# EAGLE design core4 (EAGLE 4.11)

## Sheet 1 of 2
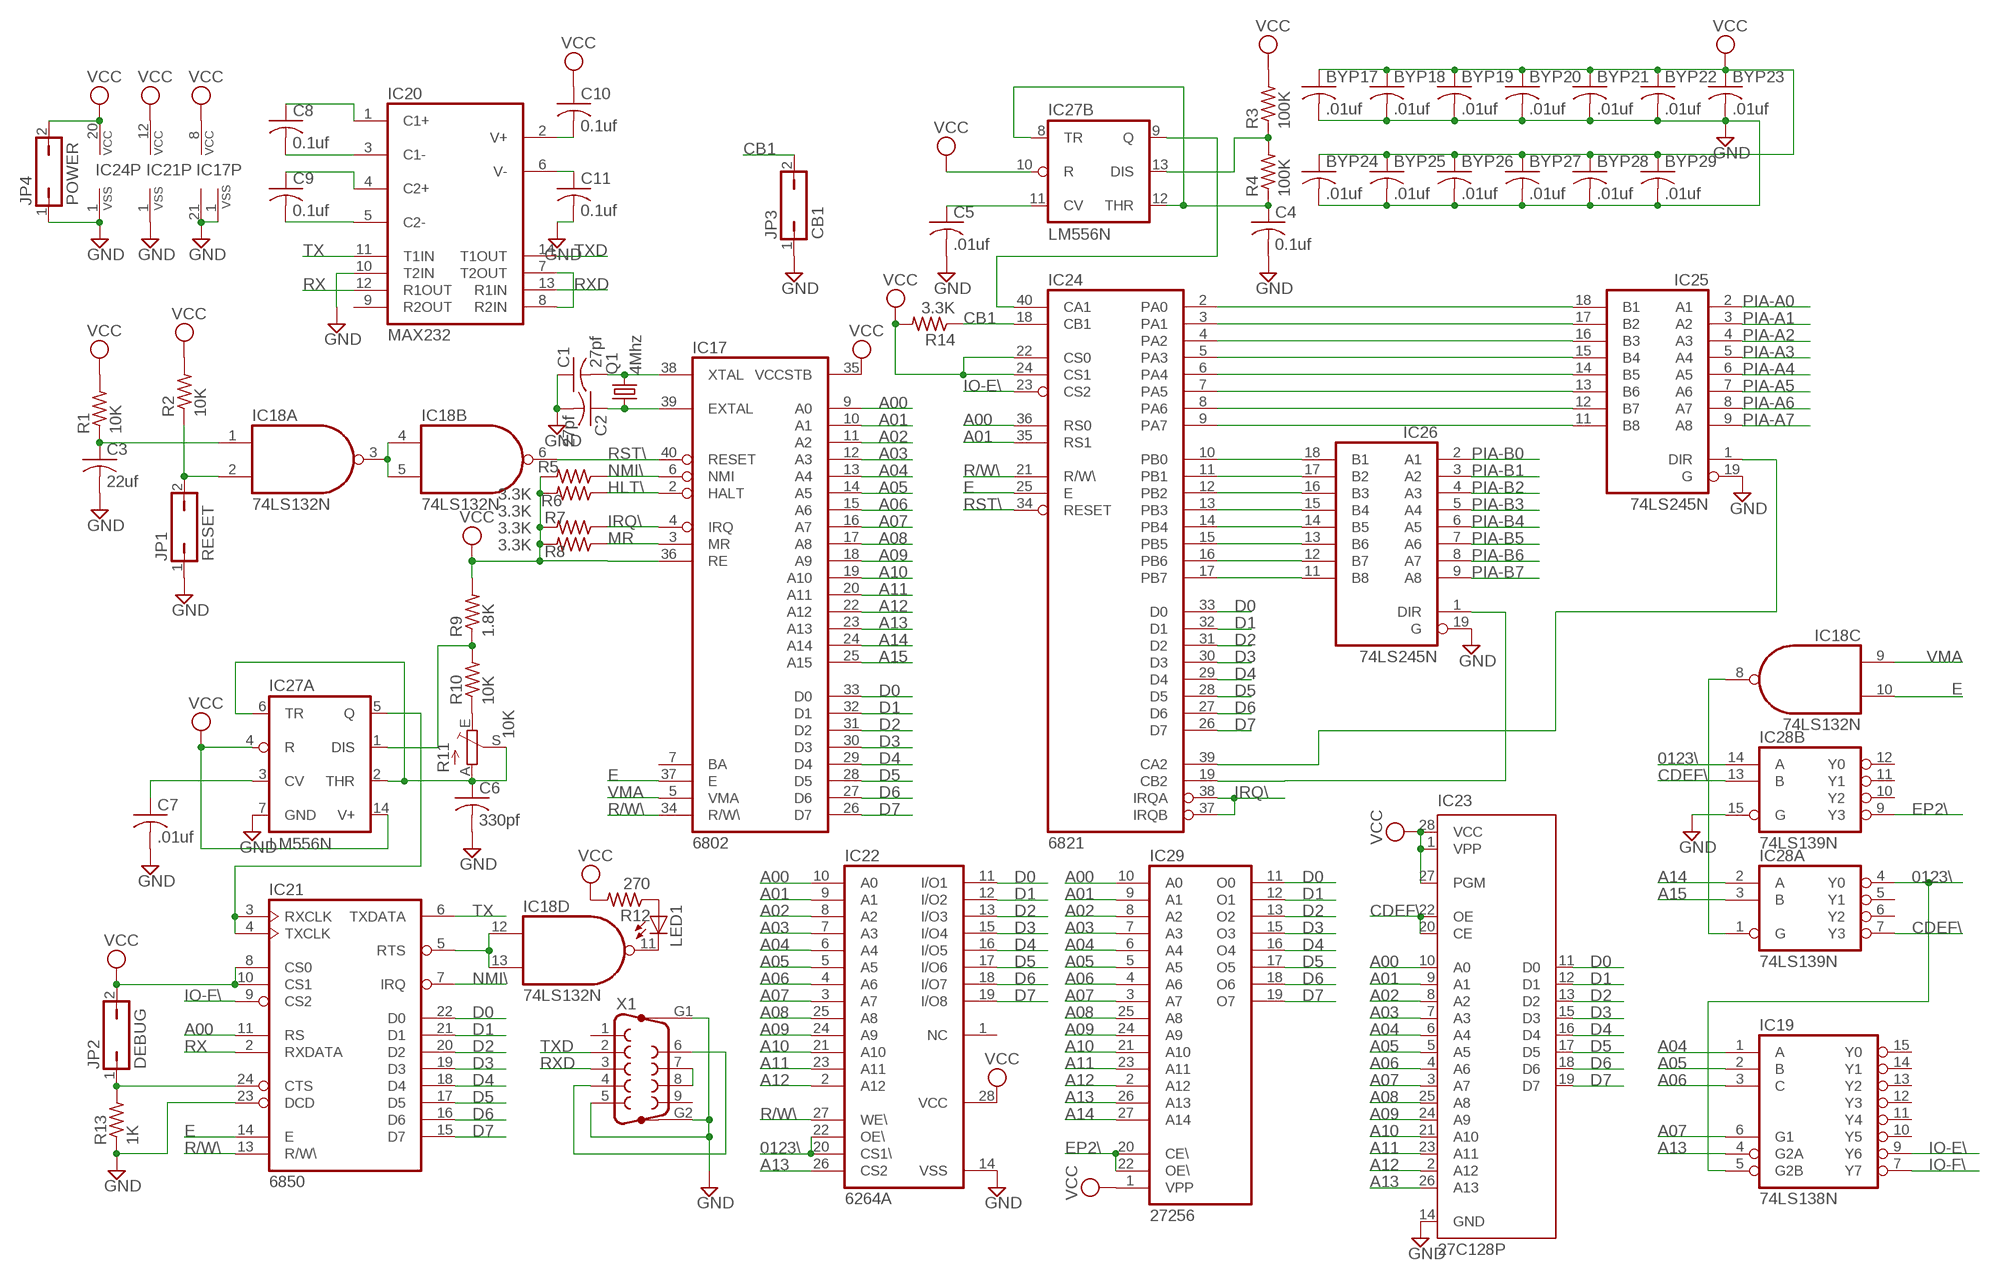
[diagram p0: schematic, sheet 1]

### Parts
BYP17  .01uf  C-US050-025X075  [C050-025X075]
BYP18  .01uf  C-US050-025X075  [C050-025X075]
BYP19  .01uf  C-US050-025X075  [C050-025X075]
BYP20  .01uf  C-US050-025X075  [C050-025X075]
BYP21  .01uf  C-US050-025X075  [C050-025X075]
BYP22  .01uf  C-US050-025X075  [C050-025X075]
BYP23  .01uf  C-US050-025X075  [C050-025X075]
BYP24  .01uf  C-US050-025X075  [C050-025X075]
BYP25  .01uf  C-US050-025X075  [C050-025X075]
BYP26  .01uf  C-US050-025X075  [C050-025X075]
BYP27  .01uf  C-US050-025X075  [C050-025X075]
BYP28  .01uf  C-US050-025X075  [C050-025X075]
BYP29  .01uf  C-US050-025X075  [C050-025X075]
C1  27pf  C-US050-025X075  [C050-025X075]
C2  27pf  C-US050-025X075  [C050-025X075]
C3  22uf  C-US102-043X133  [C102-043X133]
C4  0.1uf  C-US050-025X075  [C050-025X075]
C5  .01uf  C-US050-025X075  [C050-025X075]
C6  330pf  C-US050-025X075  [C050-025X075]
C7  .01uf  C-US050-025X075  [C050-025X075]
C8  0.1uf  C-US050-025X075  [C050-025X075]
C9  0.1uf  C-US050-025X075  [C050-025X075]
C10  0.1uf  C-US050-025X075  [C050-025X075]
C11  0.1uf  C-US050-025X075  [C050-025X075]
IC17  6802  [DIL40]
IC18  74LS132N  74LS00N  [DIL14]
IC19  74LS138N  [DIL16]
IC20  MAX232  [DIL16]
IC21  6850  [DIL24]
IC22  6264A  [DIL28-6]
IC23  27C128P  [DIL28-6]
IC24  6821  [DIL40]
IC25  74LS245N  [DIL20]
IC26  74LS245N  [DIL20]
IC27  LM556N  [DIL14]
IC28  74LS139N  [DIL16]
IC29  27256  [DIL28]
JP1  RESET  JP1Q  [JP1]
JP2  DEBUG  JP1Q  [JP1]
JP3  CB1  JP1Q  [JP1]
JP4  POWER  JP1Q  [JP1]
LED1  LED3MM  [LED3MM]
Q1  4Mhz  CRYTALHC18U-V  [HC18U-V]
R1  10K  R-US_0207/7  [0207/7]
R2  10K  R-US_0207/7  [0207/7]
R3  100K  R-US_0207/7  [0207/7]
R4  100K  R-US_0207/7  [0207/7]
R5  3.3K  R-US_0207/7  [0207/7]
R6  3.3K  R-US_0207/7  [0207/7]
R7  3.3K  R-US_0207/7  [0207/7]
R8  3.3K  R-US_0207/7  [0207/7]
R9  1.8K  R-US_0207/7  [0207/7]
R10  10K  R-US_0207/7  [0207/7]
R11  10K  TRIM_EU-B90P  [SP19L]
R12  270  R-US_0207/7  [0207/7]
R13  1K  R-US_0207/7  [0207/7]
R14  3.3K  R-US_0207/7  [0207/7]
X1  F09HP  [F09HP]

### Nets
0123\: IC19.5(G2B) IC22.20(CS1\) IC22.22(OE\) IC28.4(A:Y0) IC28.14(B:A)
A00: IC17.9(A0) IC21.11(RS) IC22.10(A0) IC23.10(A0) IC24.36(RS0) IC29.10(A0)
A01: IC17.10(A1) IC22.9(A1) IC23.9(A1) IC24.35(RS1) IC29.9(A1)
A02: IC17.11(A2) IC22.8(A2) IC23.8(A2) IC29.8(A2)
A03: IC17.12(A3) IC22.7(A3) IC23.7(A3) IC29.7(A3)
A04: IC17.13(A4) IC19.1(A) IC22.6(A4) IC23.6(A4) IC29.6(A4)
A05: IC17.14(A5) IC19.2(B) IC22.5(A5) IC23.5(A5) IC29.5(A5)
A06: IC17.15(A6) IC19.3(C) IC22.4(A6) IC23.4(A6) IC29.4(A6)
A07: IC17.16(A7) IC19.6(G1) IC22.3(A7) IC23.3(A7) IC29.3(A7)
A08: IC17.17(A8) IC22.25(A8) IC23.25(A8) IC29.25(A8)
A09: IC17.18(A9) IC22.24(A9) IC23.24(A9) IC29.24(A9)
A10: IC17.19(A10) IC22.21(A10) IC23.21(A10) IC29.21(A10)
A11: IC17.20(A11) IC22.23(A11) IC23.23(A11) IC29.23(A11)
A12: IC17.22(A12) IC22.2(A12) IC23.2(A12) IC29.2(A12)
A13: IC17.23(A13) IC19.4(G2A) IC22.26(CS2) IC23.26(A13) IC29.26(A13)
A14: IC17.24(A14) IC28.2(A:A) IC29.27(A14)
A15: IC17.25(A15) IC28.3(A:B)
CB1: IC24.18(CB1) JP3.2 R14.1
CDEF\: IC23.20(CE) IC23.22(OE) IC28.7(A:Y3) IC28.13(B:B)
D0: IC17.33(D0) IC21.22(D0) IC22.11(I/O1) IC23.11(D0) IC24.33(D0) IC29.11(O0)
D1: IC17.32(D1) IC21.21(D1) IC22.12(I/O2) IC23.12(D1) IC24.32(D1) IC29.12(O1)
D2: IC17.31(D2) IC21.20(D2) IC22.13(I/O3) IC23.13(D2) IC24.31(D2) IC29.13(O2)
D3: IC17.30(D3) IC21.19(D3) IC22.15(I/O4) IC23.15(D3) IC24.30(D3) IC29.15(O3)
D4: IC17.29(D4) IC21.18(D4) IC22.16(I/O5) IC23.16(D4) IC24.29(D4) IC29.16(O4)
D5: IC17.28(D5) IC21.17(D5) IC22.17(I/O6) IC23.17(D5) IC24.28(D5) IC29.17(O5)
D6: IC17.27(D6) IC21.16(D6) IC22.18(I/O7) IC23.18(D6) IC24.27(D6) IC29.18(O6)
D7: IC17.26(D7) IC21.15(D7) IC22.19(I/O8) IC23.19(D7) IC24.26(D7) IC29.19(O7)
E: IC17.37(E) IC18.10(C:I1) IC21.14(E) IC24.25(E)
EP2\: IC28.9(B:Y3) IC29.20(CE\) IC29.22(OE\)
GND [Power]: BYP17.2 BYP18.2 BYP19.2 BYP20.2 BYP21.2 BYP22.2 BYP23.2 BYP24.2 BYP25.2 BYP26.2 BYP27.2 BYP28.2 BYP29.2 C1.1 C2.2 C3.2 C4.2 C5.2 C6.2 C7.2 C11.2 IC17.1(VSS) IC17.21(VSS) IC20.10(T2IN) IC21.1(VSS) IC21.23(DCD) IC22.14(VSS) IC23.14(GND) IC24.1(VSS) IC25.19(G) IC26.19(G) IC27.7(A:GND) IC28.15(B:G) JP1.1 JP3.1 JP4.1 R13.1 X1.5 X1.G1 X1.G2 ; also sheet 2
HLT\: IC17.2(HALT) R5.1
IO-E\: IC19.9(Y6) IC24.23(CS2)
IO-F\: IC19.7(Y7) IC21.9(CS2)
IRQ\: IC17.4(IRQ) IC24.37(IRQB) IC24.38(IRQA) R7.1
MR: IC17.3(MR) R8.1
N$3: C2.1 IC17.39(EXTAL) Q1.1
N$4: C1.2 IC17.38(XTAL) Q1.2
N$5: IC24.2(PA0) IC25.18(B1)
N$6: IC18.3(A:O) IC18.4(B:I0) IC18.5(B:I1)
N$21: C3.1 IC18.1(A:I0) R1.1
N$22: IC18.2(A:I1) JP1.2 R2.1
N$23: IC21.3(RXCLK) IC21.4(TXCLK) IC27.5(A:Q)
N$24: IC24.10(PB0) IC26.18(B1)
N$25: IC24.11(PB1) IC26.17(B2)
N$27: C6.1 IC27.2(A:THR) IC27.6(A:TR) R11.A R11.S
N$28: IC27.1(A:DIS) R9.1 R10.2
N$94: IC24.12(PB2) IC26.16(B3)
N$124: IC24.13(PB3) IC26.15(B4)
N$125: IC24.14(PB4) IC26.14(B5)
N$126: IC24.15(PB5) IC26.13(B6)
N$127: IC24.16(PB6) IC26.12(B7)
N$128: IC24.17(PB7) IC26.11(B8)
N$129: IC24.3(PA1) IC25.17(B2)
N$130: IC24.4(PA2) IC25.16(B3)
N$131: IC24.5(PA3) IC25.15(B4)
N$132: IC24.6(PA4) IC25.14(B5)
N$133: IC24.7(PA5) IC25.13(B6)
N$134: IC24.8(PA6) IC25.12(B7)
N$135: IC24.9(PA7) IC25.11(B8)
N$136: IC24.19(CB2) IC26.1(DIR)
N$137: IC24.39(CA2) IC25.1(DIR)
N$138: IC24.40(CA1) IC27.9(B:Q)
N$140: C4.1 IC27.8(B:TR) IC27.12(B:THR) R4.1
N$141: IC27.13(B:DIS) R3.1 R4.2
N$142: C5.1 IC27.11(B:CV)
N$143: R10.1 R11.E
N$144: X1.4 X1.6
N$145: X1.7 X1.8
N$147: IC18.12(D:I0) IC18.13(D:I1) IC21.5(RTS)
N$148: IC18.11(D:O) LED1.K(C)
N$149: LED1.A R12.1
N$150: IC21.24(CTS) JP2.1 R13.2
N$151: IC18.8(C:O) IC28.1(A:G)
N$153: IC20.7(T2OUT) IC20.8(R2IN)
N$154: C7.1 IC27.3(A:CV)
N$155: C9.2 IC20.5(C2-)
N$156: C9.1 IC20.4(C2+)
N$157: C8.2 IC20.3(C1-)
N$158: C8.1 IC20.1(C1+)
N$159: C11.1 IC20.6(V-)
N$160: C10.2 IC20.2(V+)
NMI\: IC17.6(NMI) IC21.7(IRQ) R6.1
PIA-A0: IC25.2(A1) ; also sheet 2
PIA-A1: IC25.3(A2) ; also sheet 2
PIA-A2: IC25.4(A3) ; also sheet 2
PIA-A3: IC25.5(A4) ; also sheet 2
PIA-A4: IC25.6(A5) ; also sheet 2
PIA-A5: IC25.7(A6) ; also sheet 2
PIA-A6: IC25.8(A7) ; also sheet 2
PIA-A7: IC25.9(A8) ; also sheet 2
PIA-B0: IC26.2(A1) ; also sheet 2
PIA-B1: IC26.3(A2) ; also sheet 2
PIA-B2: IC26.4(A3) ; also sheet 2
PIA-B3: IC26.5(A4) ; also sheet 2
PIA-B4: IC26.6(A5) ; also sheet 2
PIA-B5: IC26.7(A6) ; also sheet 2
PIA-B6: IC26.8(A7) ; also sheet 2
PIA-B7: IC26.9(A8) ; also sheet 2
R/W\: IC17.34(R/W\) IC21.13(R/W\) IC22.27(WE\) IC24.21(R/W\)
RST\: IC17.40(RESET) IC18.6(B:O) IC24.34(RESET)
RX: IC20.12(R1OUT) IC21.2(RXDATA)
RXD: IC20.13(R1IN) X1.3
TX: IC20.11(T1IN) IC21.6(TXDATA)
TXD: IC20.14(T1OUT) X1.2
VCC [Power]: BYP17.1 BYP18.1 BYP19.1 BYP20.1 BYP21.1 BYP22.1 BYP23.1 BYP24.1 BYP25.1 BYP26.1 BYP27.1 BYP28.1 BYP29.1 C10.1 IC17.8(VCC) IC17.35(VCCSTB) IC17.36(RE) IC21.8(CS0) IC21.10(CS1) IC21.12(VCC) IC22.28(VCC) IC23.1(VPP) IC23.27(PGM) IC23.28(VCC) IC24.20(VCC) IC24.22(CS0) IC24.24(CS1) IC27.4(A:R) IC27.10(B:R) IC27.14(A:V+) IC29.1(VPP) JP2.2 JP4.2 R1.2 R2.2 R3.2 R5.2 R6.2 R7.2 R8.2 R9.2 R12.2 R14.2 ; also sheet 2
VMA: IC17.5(VMA) IC18.9(C:I0)
Unconnected: IC17.7(BA) IC19.10(Y5) IC19.11(Y4) IC19.12(Y3) IC19.13(Y2) IC19.14(Y1) IC19.15(Y0) IC20.9(R2OUT) IC22.1(NC) IC28.5(A:Y1) IC28.6(A:Y2) IC28.10(B:Y2) IC28.11(B:Y1) IC28.12(B:Y0) X1.1 X1.9

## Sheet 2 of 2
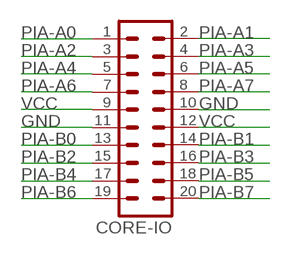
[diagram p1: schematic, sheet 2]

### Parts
CORE-IO  MA10-2  [MA10-2]

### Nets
GND [Power]: CORE-IO.10 CORE-IO.11 ; also sheet 1
PIA-A0: CORE-IO.1 ; also sheet 1
PIA-A1: CORE-IO.2 ; also sheet 1
PIA-A2: CORE-IO.3 ; also sheet 1
PIA-A3: CORE-IO.4 ; also sheet 1
PIA-A4: CORE-IO.5 ; also sheet 1
PIA-A5: CORE-IO.6 ; also sheet 1
PIA-A6: CORE-IO.7 ; also sheet 1
PIA-A7: CORE-IO.8 ; also sheet 1
PIA-B0: CORE-IO.13 ; also sheet 1
PIA-B1: CORE-IO.14 ; also sheet 1
PIA-B2: CORE-IO.15 ; also sheet 1
PIA-B3: CORE-IO.16 ; also sheet 1
PIA-B4: CORE-IO.17 ; also sheet 1
PIA-B5: CORE-IO.18 ; also sheet 1
PIA-B6: CORE-IO.19 ; also sheet 1
PIA-B7: CORE-IO.20 ; also sheet 1
VCC [Power]: CORE-IO.9 CORE-IO.12 ; also sheet 1

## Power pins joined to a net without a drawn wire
GND: IC18.7(P:GND) IC19.8(GND) IC20.15(GND) IC25.10(GND) IC26.10(GND) IC28.8(P:GND) IC29.14(GND)
VCC: IC18.14(P:VCC) IC19.16(VCC) IC20.16(VCC) IC25.20(VCC) IC26.20(VCC) IC28.16(P:VCC) IC29.28(VCC)

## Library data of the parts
BYP17-BYP29 C1-C11 = rcl:C-US: CAPACITOR, American symbol
CORE-IO = con-lstb:MA10-2: PIN HEADER
IC17 = micro-motorola:6802: MICROCONTROLLER/MEMORY DEVICE
IC18 = 74xx-us:74*00: Quad 2-input NAND gate
IC19 = 74xx-us:74*138: 3-line to 8-line DECODER/DEMULTIPLEXER
IC20 = maxim:MAX232: RS232 TRANSEIVER
IC21 = micro-motorola:6850: MICROCONTROLLER/MEMORY DEVICE
IC22 = memory-hitachi:6264A: MEMORY
IC23 = microchip:27*128: CMOS EPROM 128 K (16 K x 8)
IC24 = micro-motorola:6821: MICROCONTROLLER/MEMORY DEVICE
IC25 IC26 = 74xx-us:74*245: Octal BUS TRANSCEIVER, 3-state
IC27 = linear:*556: Dual TIMER
IC28 = 74xx-us:74*139: Dual 2-line to 4-line DECODER/DEMULTIPLEXER
IC29 = memory:27256: MEMORY
JP1-JP4 = jumper:JP1Q: JUMPER
LED1 = led:LED: LED
Q1 = crystal:CRYTAL: CRYSTAL
R1-R10 R12-R14 = rcl:R-US_: RESISTOR, American symbol
R11 = pot:TRIM_EU-: POTENTIOMETER
X1 = con-subd:F09HP: SUB-D

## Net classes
1 Power: width 0.508 mm, drill 0.254 mm, clearance 0.254 mm

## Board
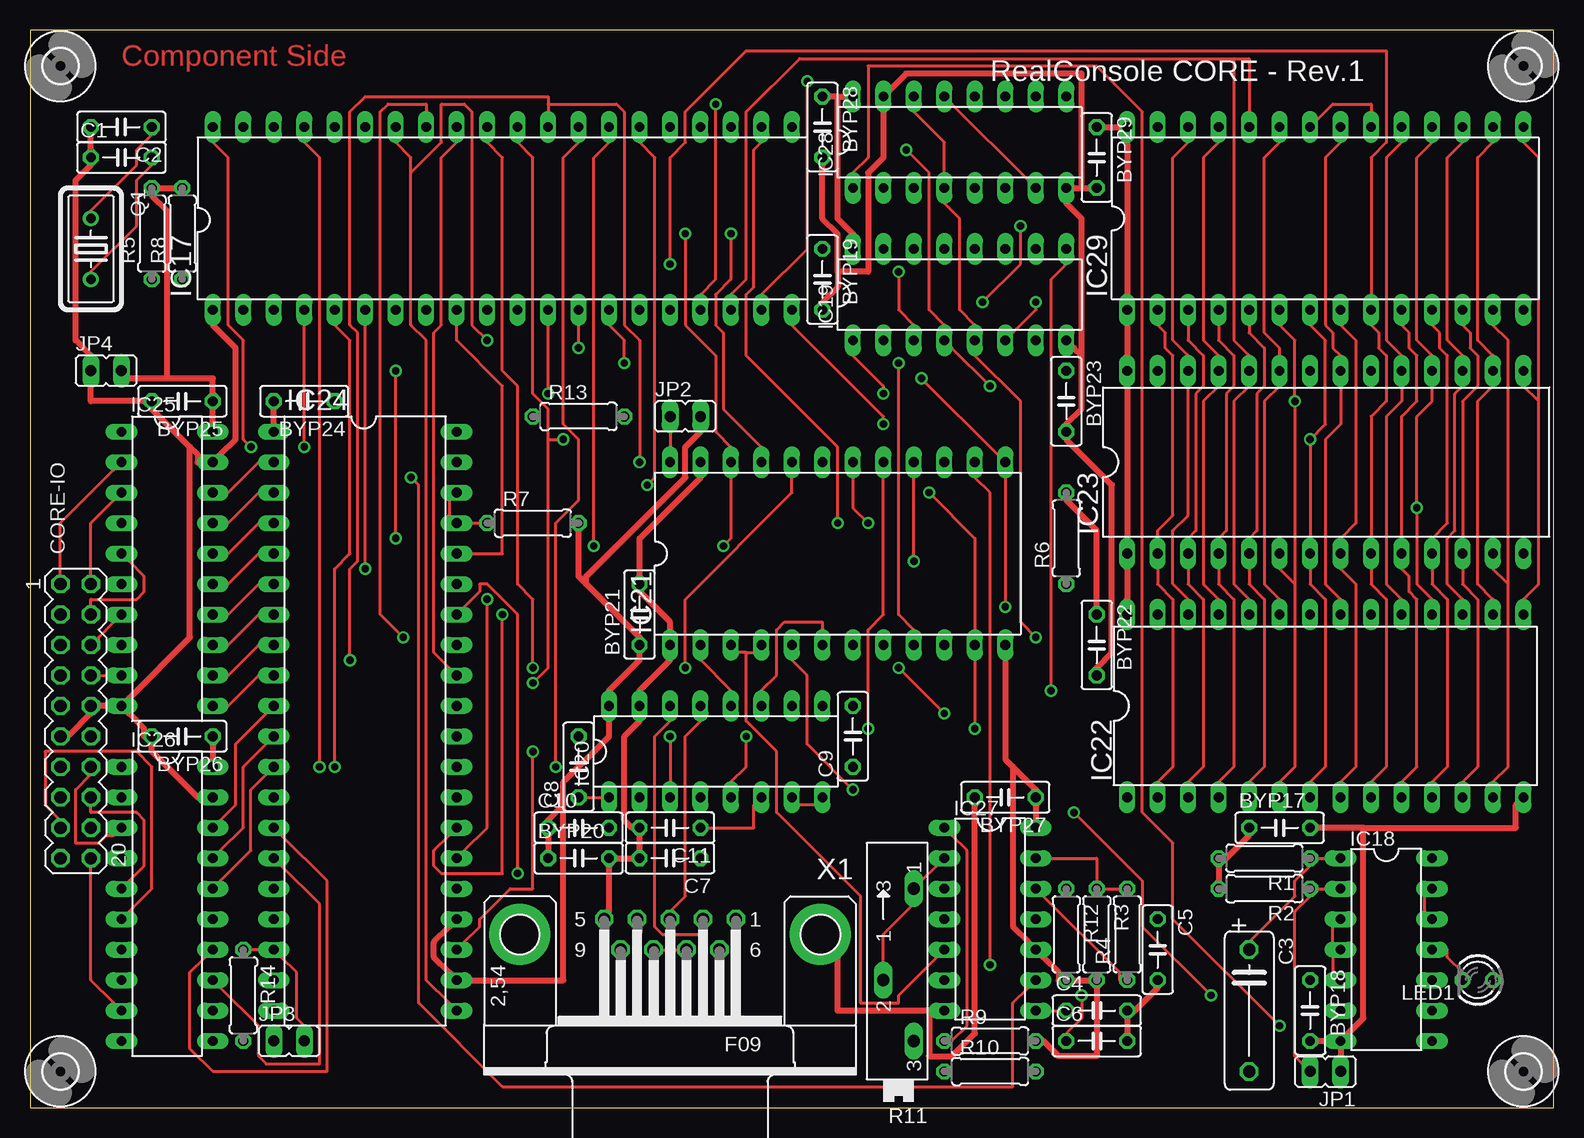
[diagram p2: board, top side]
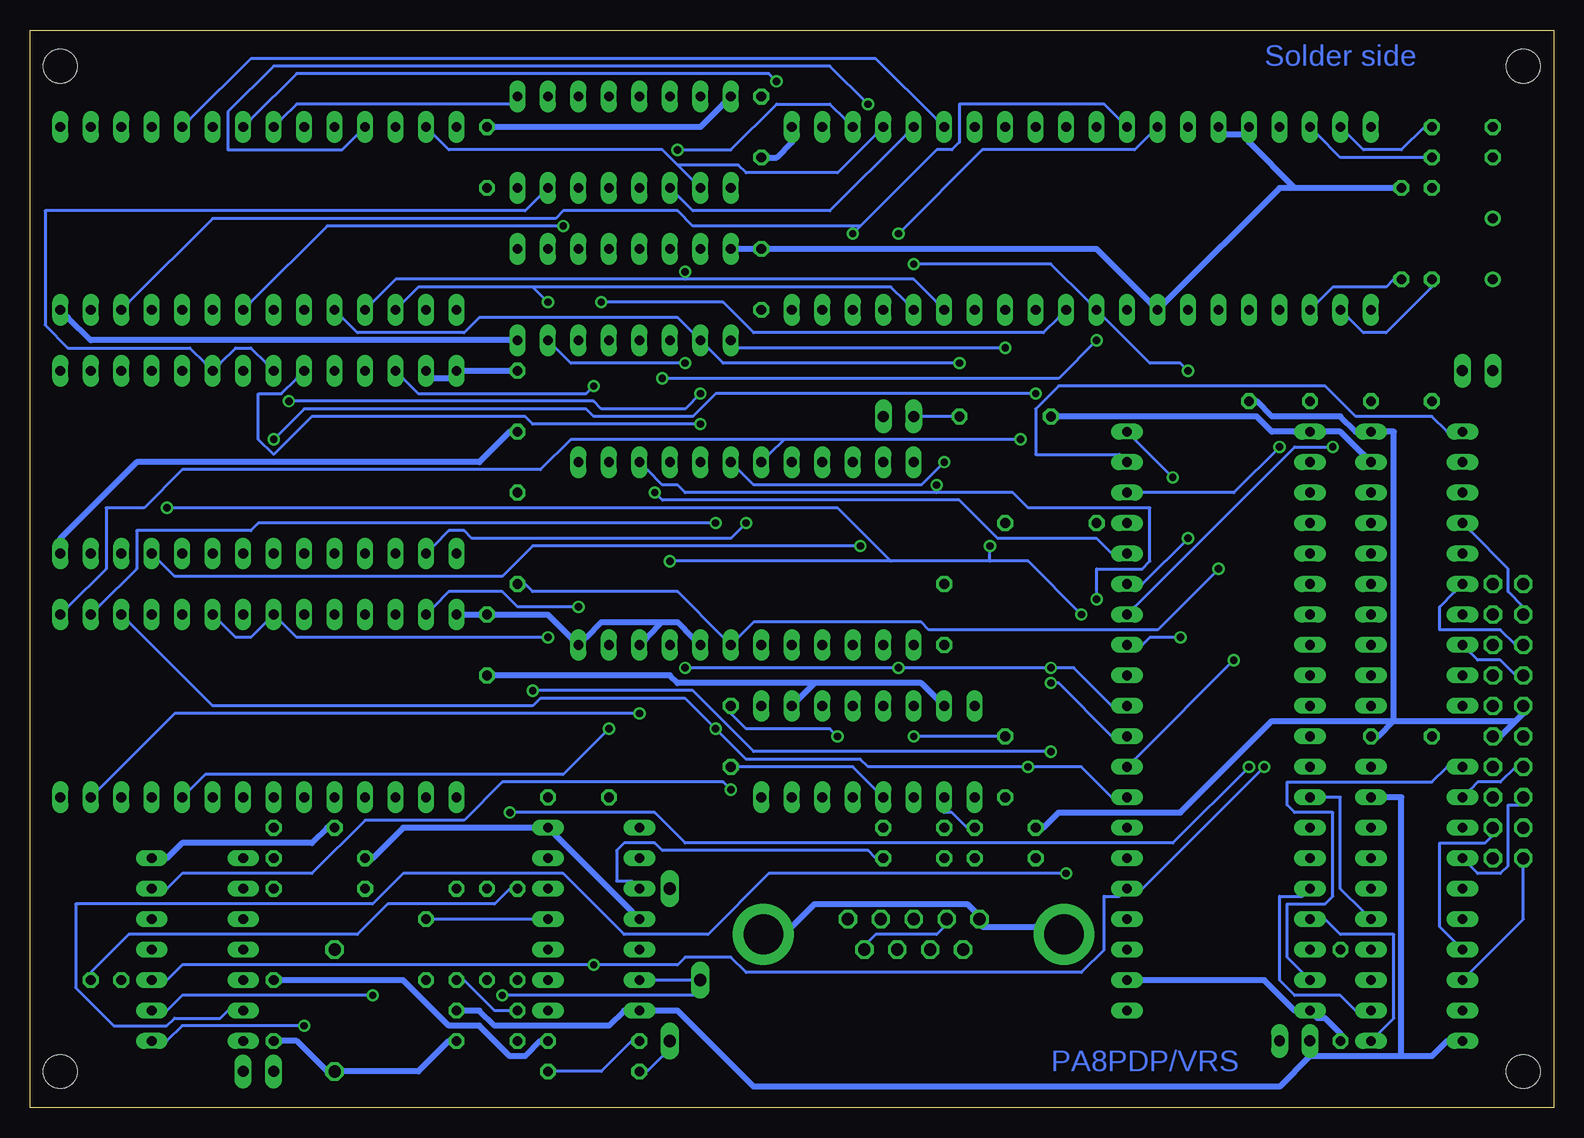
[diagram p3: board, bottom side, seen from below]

Size 126.98 x 89.84 mm. Coordinates in mm from the lower left corner, seen from the top.
Outline: 0,0 126.98,0 126.98,89.84 0,89.84 0,0
Copper layers (1*16): Top 0.035mm / dielectric 1.5mm / Bottom 0.035mm
Design rules "olimex10mil": minimum track width 10mil, minimum drill 24mil, track to track 10mil, track to pad 10mil, pad to pad 10mil, via to via 10mil, smd to smd 10mil, copper to edge 40mil, drill to drill 10mil, minimum pad ring 10mil, minimum via ring 8mil, stop-mask expansion 0mil, vias tented up to drill 0mil, thermal gap 10mil

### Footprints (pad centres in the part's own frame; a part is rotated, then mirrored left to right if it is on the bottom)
C050-025X075 = drill 0.813 octagon: 1 -2.54,0; 2 2.54,0
C102-043X133 = drill 1.016 octagon: 1 -5.08,0; 2 5.08,0
MA10-2 = drill 1.016 octagon: 1 -11.43,-1.27; 2 -11.43,1.27; 3 -8.89,-1.27; 4 -8.89,1.27; 5 -6.35,-1.27; 6 -6.35,1.27; 7 -3.81,-1.27; 8 -3.81,1.27; 9 -1.27,-1.27; 10 -1.27,1.27; 11 1.27,-1.27; 12 1.27,1.27; 13 3.81,-1.27; 14 3.81,1.27; 15 6.35,-1.27; 16 6.35,1.27; 17 8.89,-1.27; 18 8.89,1.27; 19 11.43,-1.27; 20 11.43,1.27
DIL40 = drill 0.813 long: 1 -24.13,-7.62; 2 -21.59,-7.62; 3 -19.05,-7.62; 4 -16.51,-7.62; 5 -13.97,-7.62; 6 -11.43,-7.62; 7 -8.89,-7.62; 8 -6.35,-7.62; 9 -3.81,-7.62; 10 -1.27,-7.62; 11 1.27,-7.62; 12 3.81,-7.62; 13 6.35,-7.62; 14 8.89,-7.62; 15 11.43,-7.62; 16 13.97,-7.62; 17 16.51,-7.62; 18 19.05,-7.62; 19 21.59,-7.62; 20 24.13,-7.62; 21 24.13,7.62; 22 21.59,7.62; 23 19.05,7.62; 24 16.51,7.62; 25 13.97,7.62; 26 11.43,7.62; 27 8.89,7.62; 28 6.35,7.62; 29 3.81,7.62; 30 1.27,7.62; 31 -1.27,7.62; 32 -3.81,7.62; 33 -6.35,7.62; 34 -8.89,7.62; 35 -11.43,7.62; 36 -13.97,7.62; 37 -16.51,7.62; 38 -19.05,7.62; 39 -21.59,7.62; 40 -24.13,7.62
DIL14 = drill 0.813 long: 1 -7.62,-3.81; 2 -5.08,-3.81; 3 -2.54,-3.81; 4 0,-3.81; 5 2.54,-3.81; 6 5.08,-3.81; 7 7.62,-3.81; 8 7.62,3.81; 9 5.08,3.81; 10 2.54,3.81; 11 0,3.81; 12 -2.54,3.81; 13 -5.08,3.81; 14 -7.62,3.81
DIL16 = drill 0.813 long: 1 -8.89,-3.81; 2 -6.35,-3.81; 3 -3.81,-3.81; 4 -1.27,-3.81; 5 1.27,-3.81; 6 3.81,-3.81; 7 6.35,-3.81; 8 8.89,-3.81; 9 8.89,3.81; 10 6.35,3.81; 11 3.81,3.81; 12 1.27,3.81; 13 -1.27,3.81; 14 -3.81,3.81; 15 -6.35,3.81; 16 -8.89,3.81
DIL24 = drill 0.813 long: 1 -13.97,-7.62; 2 -11.43,-7.62; 3 -8.89,-7.62; 4 -6.35,-7.62; 5 -3.81,-7.62; 6 -1.27,-7.62; 7 1.27,-7.62; 8 3.81,-7.62; 9 6.35,-7.62; 10 8.89,-7.62; 11 11.43,-7.62; 12 13.97,-7.62; 13 13.97,7.62; 14 11.43,7.62; 15 8.89,7.62; 16 6.35,7.62; 17 3.81,7.62; 18 1.27,7.62; 19 -1.27,7.62; 20 -3.81,7.62; 21 -6.35,7.62; 22 -8.89,7.62; 23 -11.43,7.62; 24 -13.97,7.62
DIL28-6 = drill 0.813 long: 1 -16.51,-7.62; 2 -13.97,-7.62; 3 -11.43,-7.62; 4 -8.89,-7.62; 5 -6.35,-7.62; 6 -3.81,-7.62; 7 -1.27,-7.62; 8 1.27,-7.62; 9 3.81,-7.62; 10 6.35,-7.62; 11 8.89,-7.62; 12 11.43,-7.62; 13 13.97,-7.62; 14 16.51,-7.62; 15 16.51,7.62; 16 13.97,7.62; 17 11.43,7.62; 18 8.89,7.62; 19 6.35,7.62; 20 3.81,7.62; 21 1.27,7.62; 22 -1.27,7.62; 23 -3.81,7.62; 24 -6.35,7.62; 25 -8.89,7.62; 26 -11.43,7.62; 27 -13.97,7.62; 28 -16.51,7.62
DIL20 = drill 0.813 long: 1 -11.43,-3.81; 2 -8.89,-3.81; 3 -6.35,-3.81; 4 -3.81,-3.81; 5 -1.27,-3.81; 6 1.27,-3.81; 7 3.81,-3.81; 8 6.35,-3.81; 9 8.89,-3.81; 10 11.43,-3.81; 11 11.43,3.81; 12 8.89,3.81; 13 6.35,3.81; 14 3.81,3.81; 15 1.27,3.81; 16 -1.27,3.81; 17 -3.81,3.81; 18 -6.35,3.81; 19 -8.89,3.81; 20 -11.43,3.81
DIL28 = drill 0.813 long: 1 -16.51,-7.62; 2 -13.97,-7.62; 3 -11.43,-7.62; 4 -8.89,-7.62; 5 -6.35,-7.62; 6 -3.81,-7.62; 7 -1.27,-7.62; 8 1.27,-7.62; 9 3.81,-7.62; 10 6.35,-7.62; 11 8.89,-7.62; 12 11.43,-7.62; 13 13.97,-7.62; 14 16.51,-7.62; 15 16.51,7.62; 16 13.97,7.62; 17 11.43,7.62; 18 8.89,7.62; 19 6.35,7.62; 20 3.81,7.62; 21 1.27,7.62; 22 -1.27,7.62; 23 -3.81,7.62; 24 -6.35,7.62; 25 -8.89,7.62; 26 -11.43,7.62; 27 -13.97,7.62; 28 -16.51,7.62
JP1 = drill 0.914 long: 1 0,-1.27; 2 0,1.27
LED3MM = drill 0.813 octagon: A -1.27,0; K 1.27,0
HC18U-V = drill 0.813 round: 1 -2.54,0; 2 2.54,0
0207/7 = drill 0.813 octagon: 1 -3.81,0; 2 3.81,0
SP19L = drill 1.016 long: A 5.715,-1.27; E -6.985,-1.27; S -1.905,1.27
2,8 = hole 2.8: 0,0
F09HP = drill 1.016 octagon: 1 -5.486,-1.27; 2 -2.743,-1.27; 3 0,-1.27; 4 2.743,-1.27; 5 5.486,-1.27; 6 -4.115,1.27; 7 -1.372,1.27; 8 1.372,1.27; 9 4.115,1.27 | drill 3.302 pad 5.08 round: G1 -12.522,0; G2 12.522,0

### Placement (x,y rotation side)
BYP17  104.14,23.33 0 top
BYP18  106.68,8.09 270 top
BYP19  66.04,69.05 270 top
BYP20  45.71,20.79 0 top
BYP21  50.79,41.11 90 top
BYP22  88.9,38.57 270 top
BYP23  86.36,58.89 270 top
BYP24  22.86,58.89 180 top
BYP25  12.69,58.89 180 top
BYP26  12.69,30.95 180 top
BYP27  81.28,25.87 180 top
BYP28  66.04,81.75 270 top
BYP29  88.9,79.21 270 top
C1  7.62,79.21 0 top
C2  7.62,81.75 180 top
C3  101.59,8.09 270 top
C4  88.9,8.09 0 top
C5  93.98,13.17 270 top
C6  88.9,5.55 0 top
C7  53.34,20.79 180 top
C8  45.71,28.41 90 top
C9  68.58,30.95 90 top
C10  45.71,23.33 0 top
C11  53.34,23.33 180 top
CORE-IO  3.81,32.22 270 top
IC17  39.36,74.13 0 top
IC18  113.03,13.17 270 top
IC19  77.47,67.78 0 top
IC20  57.14,29.68 0 top
IC21  67.31,46.19 0 top
IC22  107.95,33.49 0 top
IC23  107.95,53.81 0 top
IC24  27.94,32.22 270 top
IC25  11.42,44.92 270 top
IC26  11.42,16.98 270 top
IC27  80.01,15.71 270 top
IC28  77.47,80.48 0 top
IC29  107.95,74.13 0 top
JP1  107.95,3.01 90 top
JP2  54.6,57.62 270 top
JP3  21.59,5.55 270 top
JP4  6.34,61.43 270 top
LED1  120.65,10.63 180 top
Q1  5.08,71.59 270 top
R1  102.87,20.79 180 top
R2  102.87,18.25 180 top
R3  88.9,14.44 270 top
R4  91.44,14.44 90 top
R5  10.15,72.86 90 top
R6  86.36,47.46 90 top
R7  41.9,48.73 0 top
R8  12.69,72.86 90 top
R9  80.01,5.55 0 top
R10  80.01,3.01 0 top
R11  72.39,12.54 90 top
R12  86.36,14.44 270 top
R13  45.71,57.62 0 top
R14  17.78,9.36 270 top
U$3  [2,8]  2.54,86.83 0 top
U$4  [2,8]  2.54,3.01 0 top
U$5  [2,8]  124.45,86.83 0 top
U$6  [2,8]  124.45,3.01 0 top
X1  53.34,14.44 180 top

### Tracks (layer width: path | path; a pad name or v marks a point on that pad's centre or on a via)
0123\  (via drill 0.61)
  Top 0.254: IC28.14 73.66,83.02 76.2,80.48 76.2,77.94 IC28.4 76.2,75.4 77.47,74.13 77.47,66.51 78.73,65.24 IC19.5 78.73,62.7 82.55,58.89 82.55,40.48 v83.81,39.2
  Bottom 0.254: IC22.20 111.12,40.48 109.85,39.2 108.58,39.2 107.31,40.48 IC22.22 106.04,40.48 104.77,39.2 v83.81,39.2
A00  (via drill 0.61)
  Top 0.254: IC24.36 36.82,46.19 39.36,46.19 39.36,60.16 35.55,63.97 35.55,65.24 IC17.9 | v78.73,31.58 78.73,37.3 IC21.11 78.73,39.84 78.73,47.46 v74.93,51.27 | IC22.10 114.3,27.14 115.56,28.41 115.56,42.38 114.93,43.02 114.93,44.28 114.3,44.92 IC23.10 114.3,47.46 114.3,57.62 115.56,58.89 115.56,62.7 114.93,63.34 114.93,64.61 114.3,65.24 IC29.10
  Bottom 0.254: v78.73,31.58 82.55,27.77 112.39,27.77 113.66,26.5 IC22.10 | v74.93,51.27 74.29,50.63 49.52,50.63 46.35,47.46 38.09,47.46 36.82,46.19 IC24.36
A01  (via drill 0.61)
  Top 0.254: v30.48,47.46 v30.48,61.43 | IC22.9 111.76,27.14 113.03,28.41 113.03,42.38 111.76,43.65 111.76,44.92 IC23.9 111.76,47.46 111.76,57.62 113.03,58.89 113.03,62.7 112.39,63.34 112.39,64.61 111.76,65.24 IC29.9 111.76,67.78 111.76,79.21 113.03,80.48 113.03,88.1 59.68,88.1 54.6,83.02 54.6,80.48 53.34,79.21 v53.34,70.32
  Bottom 0.254: v30.48,47.46 34.28,43.65 IC24.35 | v30.48,61.43 31.11,62.06 33.65,62.06 37.46,65.88 IC17.10 38.73,67.14 41.9,70.32 v53.34,70.32
A02  (via drill 0.61)
  Top 0.254: IC22.8 109.22,27.14 110.48,28.41 110.48,43.65 109.22,44.92 IC23.8 109.22,47.46 110.48,48.73 110.48,63.97 109.22,65.24 IC29.8 | v79.37,67.14 82.55,70.32 v82.55,73.5
  Bottom 0.254: v79.37,67.14 69.21,67.14 66.67,64.61 42.54,64.61 41.27,65.88 IC17.11 | v82.55,73.5 102.23,73.5 108.58,67.14 IC29.8
A03  (via drill 0.61)
  Top 0.254: IC22.7 106.68,27.14 107.95,28.41 107.95,42.38 106.68,43.65 106.68,44.92 IC23.7 106.68,47.46 v106.68,55.71 107.95,56.98 107.95,63.97 106.68,65.24 IC29.7 | v43.17,59.52 43.17,65.24 IC17.12
  Bottom 0.254: v43.17,59.52 69.84,59.52 71.75,57.62 80.01,57.62 80.64,58.25 104.14,58.25 v106.68,55.71
A04  (via drill 0.61)
  Top 0.254: v45.71,63.34 45.71,65.24 IC17.13 | 105.41,43.65 105.41,28.41 104.14,27.14 IC22.6 | 105.41,43.65 104.14,44.92 IC23.6 | 105.41,43.65 v105.41,58.89 105.41,63.97 104.14,65.24 IC29.6 | v71.12,59.52 71.12,60.16 68.58,62.7 IC19.1
  Bottom 0.254: v45.71,63.34 67.94,63.34 IC19.1 | v71.12,59.52 72.39,58.25 79.37,58.25 80.01,58.89 v105.41,58.89
A05  (via drill 0.61)
  Top 0.254: IC22.5 101.59,27.14 102.87,28.41 102.87,42.38 101.59,43.65 101.59,44.92 IC23.5 101.59,47.46 102.23,48.09 102.23,59.52 102.87,60.16 102.87,63.34 101.59,64.61 101.59,65.24 IC29.5 | v49.52,62.06 49.52,63.97 48.25,65.24 IC17.14
  Bottom 0.254: IC29.5 100.96,65.88 99.69,64.61 90.8,64.61 89.53,65.88 73.02,65.88 71.75,64.61 IC19.2 70.48,63.34 69.21,62.06 v49.52,62.06
A06  (via drill 0.61)
  Top 0.254: IC22.4 99.06,27.14 100.33,28.41 100.33,42.38 99.06,43.65 99.06,44.92 IC23.4 99.06,47.46 99.69,48.09 99.69,59.52 100.33,60.16 100.33,62.7 99.06,63.97 99.06,65.24 IC29.4 | v72.39,69.69 72.39,66.51 73.66,65.24 IC19.3
  Bottom 0.254: 72.39,69.05 96.52,69.05 98.42,67.14 IC29.4 | 72.39,69.05 53.34,69.05 51.43,67.14 IC17.15 | 72.39,69.05 v72.39,69.69
A07  (via drill 0.61)
  Top 0.254: IC22.3 96.52,27.14 97.79,28.41 97.79,42.38 96.52,43.65 96.52,44.92 IC23.3 96.52,47.46 97.15,48.09 97.15,59.52 97.79,60.16 97.79,62.7 96.52,63.97 96.52,65.24 IC29.3 | v83.81,67.14 83.81,66.51 81.91,64.61 IC19.6
  Bottom 0.254: 85.09,68.41 v83.81,67.14 | 85.09,68.41 94.61,68.41 95.88,67.14 IC29.3 | 85.09,68.41 55.24,68.41 53.97,67.14 IC17.16
A08  (via drill 0.61)
  Top 0.254: IC22.25 99.06,42.38 97.79,43.65 97.79,58.89 99.06,60.16 IC23.25 99.06,62.7 97.79,63.97 97.79,79.21 99.06,80.48 IC29.25 | v57.14,83.66 57.14,69.05 55.88,67.78 IC17.17
  Bottom 0.254: v57.14,83.66 60.32,86.83 106.68,86.83 110.48,83.02 110.48,79.84 100.96,79.84 99.69,81.11 IC29.25
A09
  Top 0.254: IC22.24 101.59,42.38 100.33,43.65 100.33,58.89 101.59,60.16 IC23.24 101.59,62.7 100.33,63.97 100.33,87.47 | 100.33,87.47 101.59,87.47 101.59,83.02 IC29.24 | 100.33,87.47 64.13,87.47 59.68,83.02 59.68,69.05 58.41,67.78 IC17.18
A10  (via drill 0.61)
  Top 0.254: IC22.21 109.22,42.38 107.95,43.65 107.95,55.71 109.22,56.98 109.22,60.16 IC23.21 109.22,62.7 108.58,63.34 108.58,64.61 107.95,65.24 107.95,79.21 109.22,80.48 IC29.21 | v64.77,85.56 64.77,71.59 60.95,67.78 IC17.19
  Bottom 0.254: v64.77,85.56 65.4,86.19 104.77,86.19 108.58,82.39 IC29.21
A11  (via drill 0.61)
  Top 0.254: IC22.23 104.14,42.38 102.87,43.65 102.87,58.89 104.14,60.16 IC23.23 104.14,62.7 104.14,63.34 102.87,64.61 102.87,79.21 104.14,80.48 IC29.23 | v71.12,56.98 71.12,57.62 63.49,65.24 IC17.20
  Bottom 0.254: v71.12,56.98 85.09,56.98 85.72,57.62 103.5,57.62 106.68,54.45 107.95,55.71 107.95,59.52 106.04,59.52 104.77,60.8 IC23.23
A12  (via drill 0.61)
  Top 0.254: IC22.2 93.98,27.14 95.25,28.41 95.25,42.38 93.98,43.65 93.98,44.92 IC23.2 93.98,47.46 93.98,48.09 95.25,49.37 95.25,62.7 94.61,63.34 94.61,64.61 93.98,65.24 IC29.2 | v67.31,48.73 67.31,55.08 59.68,62.7 59.68,67.78 60.32,68.41 60.32,79.84 60.95,80.48 IC17.22
  Bottom 0.254: v67.31,48.73 68.58,47.46 90.17,47.46 90.8,48.09 92.07,48.09 93.34,46.82 IC23.2
A13  (via drill 0.61)
  Top 0.254: v73.02,79.84 74.93,77.94 74.93,66.51 76.2,65.24 IC19.4 76.83,63.34 v80.01,60.16 | IC22.26 96.52,42.38 95.25,43.65 95.25,48.09 96.52,49.37 96.52,60.16 IC23.26 96.52,62.7 95.25,63.97 95.25,79.21 96.52,80.48 IC29.26
  Bottom 0.254: v73.02,79.84 68.58,79.84 64.77,83.66 60.32,83.66 59.05,82.39 IC17.23 | v80.01,60.16 80.64,59.52 94.61,59.52 95.88,60.8 IC23.26
A14
  Bottom 0.254: 73.02,78.58 74.29,79.84 92.07,79.84 93.34,81.11 IC29.27 | 73.02,78.58 71.75,77.3 IC28.2 | 73.02,78.58 67.94,78.58 67.31,77.94 59.68,77.94 56.51,81.11 IC17.24
A15
  Bottom 0.254: IC17.25 53.97,81.11 60.32,74.77 71.75,74.77 73.02,76.03 IC28.3
CB1
  Top 0.254: R14.1 18.41,13.17 19.05,13.17 IC24.18 20.95,12.54 22.22,11.27 22.22,7.46 22.86,6.82 JP3.2
CDEF\
  Top 0.254: IC28.13 76.83,83.66 83.18,77.3 IC28.7
  Bottom 0.254: IC23.22 107.31,62.06 108.58,63.34 109.85,63.34 111.12,62.06 IC23.20 112.39,62.06 113.66,63.34 123.82,63.34 125.73,65.24 125.73,74.77 85.72,74.77 84.45,76.03 IC28.7
D0  (via drill 0.61)
  Top 0.254: IC22.11 116.84,27.14 118.11,28.41 118.11,42.38 116.84,43.65 116.84,44.92 IC23.11 116.84,47.46 118.11,48.73 118.11,62.7 117.47,63.34 117.47,64.61 116.84,65.24 IC29.11 | v31.11,39.2 29.21,41.11 29.21,83.02 29.84,83.66 33.02,83.66 33.02,83.02 IC17.33 | v54.6,72.86 54.6,65.24 57.14,62.7 57.14,56.35 58.41,55.08 IC21.22 58.41,52.54 58.41,47.46 v57.78,46.82
  Bottom 0.254: v31.11,39.2 33.65,39.2 34.28,38.57 IC24.33 | v54.6,72.86 47.62,79.84 34.92,79.84 33.65,81.11 IC17.33 | v57.78,46.82 85.09,46.82 87.62,44.28 114.93,44.28 116.2,45.55 IC23.11
D1  (via drill 0.61)
  Top 0.254: IC22.12 119.38,27.14 120.65,28.41 120.65,42.38 119.38,43.65 119.38,44.92 IC23.12 119.38,47.46 119.38,58.89 120.65,60.16 120.65,62.7 120.01,63.34 120.01,64.61 119.38,65.24 IC29.12 | IC24.32 34.92,36.66 33.65,37.94 33.65,64.61 34.28,65.24 34.28,79.21 35.55,80.48 IC17.32 | v58.41,72.86 58.41,69.05 57.14,67.78 57.14,65.24 57.78,64.61 57.78,58.25 60.95,55.08 IC21.21
  Bottom 0.254: 57.78,73.5 51.43,79.84 50.16,79.84 49.52,80.48 49.52,83.66 37.46,83.66 36.19,82.39 IC17.32 | 57.78,73.5 v58.41,72.86 | 57.78,73.5 71.75,73.5 73.02,74.77 82.55,74.77 83.18,74.13 111.76,74.13 118.74,67.14 IC29.12
D2  (via drill 0.61)
  Top 0.254: 123.19,43.65 123.19,28.41 121.92,27.14 IC22.13 | 123.19,43.65 121.92,44.92 IC23.13 | 123.19,43.65 123.19,63.97 121.92,65.24 IC29.13 | v54.6,36.66 54.6,42.38 63.49,51.27 63.49,52.54 IC21.20 | v41.9,36.66 41.9,42.38 40.63,43.65 40.63,60.16 39.36,61.43 39.36,79.21 38.09,80.48 IC17.31 | v72.39,36.66 v76.2,32.85
  Bottom 0.254: IC24.31 36.82,33.49 40,36.66 v41.9,36.66 v54.6,36.66 v72.39,36.66 | v76.2,32.85 114.93,32.85 121.28,26.5 IC22.13
D3  (via drill 0.61)
  Top 0.254: 125.73,58.89 125.73,43.65 124.45,42.38 IC22.15 | 125.73,58.89 124.45,60.16 IC23.15 | 125.73,58.89 125.73,79.21 124.45,80.48 IC29.15 | v41.9,35.39 43.17,36.66 43.17,55.71 | 43.17,55.71 43.17,58.25 41.9,59.52 41.9,79.21 40.63,80.48 IC17.30 | 43.17,55.71 v44.45,55.71
  Bottom 0.254: v41.9,35.39 41.27,35.39 36.82,30.95 IC24.30 | 64.13,55.71 65.4,54.45 IC21.19 | v44.45,55.71 64.13,55.71 | 64.13,55.71 81.91,55.71 84.45,53.17 114.3,53.17 117.47,50 120.65,50 120.65,44.92 123.82,41.74 IC22.15
D4  (via drill 0.61)
  Top 0.254: IC22.16 121.92,42.38 120.65,43.65 120.65,58.89 121.92,60.16 IC23.16 121.92,62.7 120.65,63.97 120.65,79.21 121.92,80.48 IC29.16 | v26.67,37.3 26.67,44.92 27.3,45.55 27.3,64.61 26.67,65.24 26.67,83.02 27.94,84.29 43.17,84.29 43.17,83.66 | 43.17,83.66 43.17,83.02 IC17.29 | v50.79,53.81 50.79,63.97 49.52,65.24 49.52,83.02 48.89,83.66 43.17,83.66 | v69.84,48.73 68.58,50 68.58,52.54 IC21.18
  Bottom 0.254: v26.67,37.3 34.92,29.04 IC24.29 | v50.79,53.81 52.7,51.91 66.67,51.91 67.94,53.17 IC21.18 | v69.84,48.73 107.95,48.73 108.58,48.09 118.11,48.09 118.11,44.92 121.28,41.74 IC22.16
D5  (via drill 0.61)
  Top 0.254: IC29.17 119.38,80.48 118.11,79.21 118.11,63.97 119.38,62.7 IC23.17 119.38,60.16 118.74,59.52 118.74,48.09 118.11,47.46 118.11,43.65 119.38,42.38 IC22.17 | v69.84,31.58 69.84,39.84 71.12,41.11 71.12,52.54 IC21.17 | v43.81,28.41 43.81,48.73 45.71,50.63 45.71,55.71 44.45,56.98 44.45,79.21 45.71,80.48 IC17.28
  Bottom 0.254: IC24.28 36.82,25.87 39.36,28.41 v43.81,28.41 57.14,28.41 57.78,29.04 67.31,29.04 v69.84,31.58 72.39,34.12 84.45,34.12 85.09,33.49 111.76,33.49 118.74,40.48 IC22.17
D6  (via drill 0.61)
  Top 0.254: IC22.18 116.84,42.38 115.56,43.65 v115.56,50 115.56,57.62 116.84,58.89 116.84,60.16 IC23.18 116.84,62.7 115.56,63.97 115.56,79.21 116.84,80.48 IC29.18 | v39.36,41.11 39.36,19.52 34.28,19.52 33.65,20.15 33.65,21.42 34.92,22.7 IC24.27 | v73.66,45.55 73.66,52.54 IC21.16 | v46.98,46.82 46.98,79.21 48.25,80.48 IC17.27
  Bottom 0.254: v39.36,41.11 43.81,45.55 46.98,45.55 | 55.24,45.55 v73.66,45.55 | 46.98,45.55 55.24,45.55 | 46.98,45.55 v46.98,46.82 | v115.56,50 59.68,50 55.24,45.55
D7  (via drill 0.61)
  Top 0.254: v38.09,42.38 38.09,23.33 36.19,21.42 IC24.26 | IC22.19 114.3,42.38 113.03,43.65 113.03,57.62 114.3,58.89 114.3,60.16 IC23.19 114.3,62.7 113.03,63.97 113.03,79.21 114.3,80.48 IC29.19 | v51.43,51.91 52.06,52.54 52.06,79.21 50.79,80.48 IC17.26
  Bottom 0.254: v38.09,42.38 38.09,44.92 34.28,44.92 33.65,45.55 33.65,50 43.81,50 45.08,51.27 51.43,51.27 | 51.43,51.27 72.39,51.27 73.02,51.91 74.29,51.91 75.56,53.17 IC21.15 | IC17.26 51.43,82.39 56.51,87.47 108.58,87.47 113.66,82.39 IC29.19 | 51.43,51.27 v51.43,51.91
E  (via drill 0.61)
  Top 0.254: v24.12,28.41 24.12,79.21 22.86,80.48 IC17.37 | v80.01,11.9 80.01,51.27 78.73,52.54 IC21.14
  Bottom 0.254: IC18.10 115.56,10.63 114.3,11.9 v80.01,11.9 73.02,11.9 72.39,12.54 68.58,12.54 67.31,11.27 39.36,11.27 37.46,13.17 37.46,17.61 36.19,17.61 IC24.25 34.28,18.25 v24.12,28.41
EP2\
  Top 0.254: IC29.22 107.31,82.39 108.58,83.66 111.76,83.66 111.76,83.02 IC29.20
  Bottom 0.254: IC28.9 86.99,83.66 104.77,83.66 106.04,82.39 IC29.22
GND
  Top 0.508: IC25.10 6.34,33.49 5.71,33.49 CORE-IO.10 5.08,32.85 3.17,30.95 CORE-IO.11 | IC26.19 13.96,25.87 10.15,29.68 10.15,30.31 BYP26.2 9.52,30.95 9.52,31.58 8.25,32.85 IC25.10 | C2.2 5.08,81.11 5.08,79.84 C1.1 5.08,78.58 3.81,77.3 3.81,63.97 5.08,62.7 JP4.1 5.08,60.16 5.08,58.89 9.52,58.89 BYP25.2 10.15,58.25 13.33,55.08 | BYP24.2 20.32,58.25 20.32,56.98 IC24.1 | IC17.1 15.23,65.24 17.14,63.34 17.14,55.71 15.87,54.45 IC25.19 13.96,53.81 13.96,54.45 13.33,55.08 | 13.33,55.08 13.33,39.2 8.25,34.12 IC25.10 | 67.31,69.69 67.31,72.86 66.04,74.13 66.04,78.58 BYP28.2 | 67.31,69.69 67.31,68.41 66.04,67.14 BYP19.2 | 87.62,76.67 88.26,76.67 BYP29.2 | 87.62,76.67 86.99,76.67 IC28.8 86.36,75.4 87.62,74.13 87.62,62.7 | 87.62,76.67 87.62,86.19 73.02,86.19 71.75,84.92 IC28.15 71.12,83.02 71.12,79.21 69.84,77.94 69.84,69.69 67.31,69.69 | 87.62,62.7 87.62,58.25 86.36,56.98 BYP23.2 86.36,55.71 90.17,51.91 90.17,37.94 88.9,36.66 BYP22.2 | 87.62,62.7 86.99,63.34 IC19.8 | X1.5 48.25,16.34 48.25,20.15 BYP20.2 48.89,20.79 50.16,20.79 C7.2 50.79,21.42 50.79,22.7 C11.2 50.16,23.33 49.52,23.96 49.52,30.95 50.79,32.22 IC20.15 50.79,34.76 53.34,37.3 IC21.1 53.34,39.84 53.34,40.48 50.79,43.02 BYP21.2 50.79,44.28 50.79,47.46 55.88,52.54 IC21.23 | 74.93,8.09 67.31,8.09 67.31,12.54 X1.G1 | 74.93,8.09 IC27.7 74.93,8.09 | 74.93,8.09 74.93,4.28 76.83,4.28 78.73,6.18 78.73,25.23 BYP27.2 | 111.12,23.33 123.82,23.33 123.82,25.23 IC22.14 | 111.12,23.33 107.31,23.33 BYP17.2 | C6.2 91.44,6.18 91.44,7.46 C4.2 92.07,8.09 93.98,10 C5.2 | BYP18.2 107.31,5.55 107.95,5.55 IC18.7 | JP1.1 109.22,4.28 109.22,4.92 IC18.7
  Top 0.508: 111.12,23.33 111.12,7.46 109.85,6.18 IC18.7
  Bottom 0.508: 12.69,4.28 20.32,4.28 | 12.69,4.28 10.15,4.28 8.88,5.55 IC26.10 | 20.32,4.28 JP3.1 20.32,4.28 | 12.69,4.28 12.69,25.87 13.96,25.87 IC26.19 | IC25.19 15.87,54.45 17.78,56.35 19.05,56.35 IC24.1 21.59,56.35 23.49,56.35 24.76,57.62 41.27,57.62 R13.1 | IC17.21 63.49,80.48 64.77,79.21 65.4,79.21 BYP28.2 | IC23.14 124.45,47.46 118.11,53.81 89.53,53.81 86.99,56.35 BYP23.2 | IC29.14 123.82,65.88 121.92,63.97 86.99,63.97 IC19.8 | X1.G2 43.17,15.08 47.62,15.08 X1.5 48.25,16.34 48.89,16.98 61.59,16.98 63.49,15.08 X1.G1 | 61.59,35.39 62.86,34.12 IC20.10 | 61.59,35.39 52.7,35.39 51.43,34.12 IC20.15 | BYP18.2 106.04,5.55 104.77,5.55 102.23,3.01 C3.2 100.96,3.01 94.61,3.01 92.07,5.55 C6.2 | C4.2 90.8,8.09 89.53,8.09 88.26,6.82 78.73,6.82 77.47,8.09 IC27.7 74.93,8.09 73.02,8.09 66.67,1.74 22.86,1.74 20.32,4.28 | 61.59,35.39 73.02,35.39 73.66,36.03 88.26,36.03 BYP22.2
HLT\
  Bottom 0.254: R5.1 10.15,68.41 13.96,64.61 15.87,64.61 17.14,65.88 IC17.2
IO-E\  (via drill 0.61)
  Top 0.254: v41.9,29.68 41.9,18.25 40,18.25 37.46,15.71 37.46,15.08 36.19,13.81 IC24.23 | v85.09,34.76 85.09,69.05 86.36,70.32 IC19.9
  Bottom 0.254: v41.9,29.68 66.67,29.68 71.75,34.76 v85.09,34.76
IO-F\  (via drill 0.61)
  Top 0.254: v72.39,62.06 72.39,41.11 73.66,39.84 IC21.9
  Bottom 0.254: v72.39,62.06 81.91,62.06 83.18,63.34 IC19.7
IRQ\  (via drill 0.61)
  Top 0.254: R7.1 37.46,48.73 36.82,48.73 IC24.37 34.92,49.37 34.92,50.63 IC24.38 | v22.86,55.08 22.86,65.24 IC17.4
  Bottom 0.254: v22.86,55.08 26.67,51.27 34.28,51.27 IC24.38
MR
  Bottom 0.254: R8.1 13.33,69.05 13.96,68.41 18.41,68.41 19.68,67.14 IC17.3
N$3
  Top 0.254: Q1.1 5.08,74.77 8.88,78.58 8.88,79.84 10.15,81.11 C2.1
  Bottom 0.254: IC17.39 17.14,81.11 15.87,79.84 12.69,79.84 10.79,81.75 C2.1
N$4
  Top 0.254: Q1.2 5.08,69.69 8.88,73.5 8.88,77.3 10.15,78.58 C1.2
  Bottom 0.254: IC17.38 19.68,81.11 17.78,79.21 10.79,79.21 C1.2
N$5
  Top 0.254: IC25.18 16.51,51.27 19.05,53.81 IC24.2
N$6
  Top 0.254: IC18.5 108.58,11.27 108.58,12.54 IC18.4 108.58,13.81 108.58,15.08 IC18.3
N$21
  Top 0.254: IC18.1 107.95,20.79 107.31,20.79 R1.1 106.68,20.15 105.41,18.88 105.41,17.61 101.59,13.81 C3.1
N$22
  Top 0.254: IC18.2 107.95,18.25 107.31,18.25 R2.1 106.68,17.61 105.41,16.34 105.41,4.28 106.04,3.64 JP1.2
N$23
  Top 0.254: 59.68,37.94 60.32,37.94 IC21.4 | 59.68,37.94 59.05,37.94 IC21.3 | 59.68,37.94 59.68,32.22 62.22,29.68 62.22,24.6 69.21,17.61 69.21,8.73 72.39,8.73 72.39,9.36 75.56,12.54 IC27.5
N$24
  Top 0.254: IC26.18 15.87,23.96 17.14,25.23 17.14,30.31 19.68,32.85 IC24.10
N$25
  Top 0.254: IC26.17 15.87,21.42 17.78,23.33 17.78,28.41 19.68,30.31 IC24.11
N$27  (via drill 0.61)
  Top 0.254: IC27.2 75.56,20.15 74.29,18.88 R11.A 73.66,16.98 71.12,14.44 71.12,11.9 R11.S | v87.62,9.36 87.62,7.46 86.36,6.18 C6.1
  Bottom 0.254: IC27.6 74.93,10.63 71.75,10.63 R11.S 71.12,9.36 v87.62,9.36
N$28
  Top 0.254: IC27.1 76.83,22.7 78.1,21.42 78.1,6.82 76.83,5.55 R9.1
  Bottom 0.254: R9.1 76.83,5.55 79.37,3.01 83.18,3.01 R10.2
N$94
  Top 0.254: IC26.16 15.87,18.88 18.41,21.42 18.41,26.5 19.68,27.77 IC24.12
N$124
  Bottom 0.254: IC26.15 15.87,16.34 17.78,18.25 17.78,25.87 19.05,25.87 IC24.13
N$125
  Top 0.254: IC26.14 14.6,12.54 13.33,11.27 13.33,4.92 15.23,3.01 24.76,3.01 24.76,18.88 20.95,22.7 IC24.14
N$126
  Top 0.254: IC26.13 15.87,10 19.05,6.82 19.05,4.28 19.68,3.64 24.12,3.64 24.12,16.98 20.95,20.15 IC24.15
N$127
  Bottom 0.254: IC26.12 16.51,8.09 17.78,9.36 21.59,9.36 22.86,10.63 22.86,17.61 20.95,17.61 IC24.16
N$128
  Bottom 0.254: IC26.11 14.6,6.18 13.33,7.46 13.33,14.44 17.78,14.44 19.05,15.71 IC24.17
N$129
  Top 0.254: IC25.17 16.51,48.73 19.05,51.27 IC24.3
N$130
  Top 0.254: IC25.16 16.51,46.19 19.05,48.73 IC24.4
N$131
  Top 0.254: IC25.15 16.51,43.65 19.05,46.19 IC24.5
N$132
  Top 0.254: IC25.14 16.51,41.11 19.05,43.65 IC24.6
N$133
  Top 0.254: IC25.13 16.51,38.57 19.05,41.11 IC24.7
N$134
  Top 0.254: IC25.12 16.51,36.03 19.05,38.57 IC24.8
N$135
  Top 0.254: IC25.11 16.51,33.49 19.05,36.03 IC24.9
N$136
  Bottom 0.254: IC24.19 20.95,11.27 22.22,12.54 22.22,16.98 19.05,16.98 18.41,17.61 18.41,24.6 21.59,24.6 22.22,25.23 22.22,27.14 10.15,27.14 8.88,28.41 IC26.1
N$137
  Bottom 0.254: IC25.1 8.88,56.35 10.15,57.62 16.51,57.62 19.05,60.16 41.27,60.16 43.17,58.25 43.17,54.45 36.19,54.45 IC24.39
N$138  (via drill 0.61)
  Top 0.254: v31.75,52.54 32.38,51.91 32.38,8.73 39.36,1.74 81.91,1.74 81.91,8.73 83.18,10 IC27.9
  Bottom 0.254: v31.75,52.54 34.92,55.71 IC24.40
N$140
  Top 0.254: IC27.8 85.09,8.09 85.72,8.09 C4.1 | IC27.12 84.45,17.61 90.8,11.27 90.8,10.63 R4.1
  Bottom 0.254: R4.1 90.8,10.63 88.26,8.09 86.99,8.09 C4.1
N$141
  Top 0.254: R4.2 90.8,18.25 89.53,18.25 R3.1 88.9,18.88 88.9,20.79 85.09,20.79 IC27.13
N$142
  Bottom 0.254: IC27.11 85.09,15.71 93.34,15.71 C5.1
N$143
  Bottom 0.254: R10.1 75.56,3.01 74.29,4.28 73.66,4.28 R11.E
N$144
  Bottom 0.254: X1.4 50.79,15.08 51.43,14.44 56.51,14.44 57.14,13.81 X1.6
N$145
  Top 0.254: X1.8 52.7,13.17 53.97,13.17 X1.7
N$147  (via drill 0.61)
  Top 0.254: IC18.12 116.2,16.34 116.2,17.61 IC18.13 | v68.58,26.5 64.77,30.31 64.77,36.03 63.49,37.3 IC21.5
  Bottom 0.254: v68.58,26.5 69.21,27.14 87.62,27.14 90.8,23.96 99.06,23.96 103.5,19.52 114.3,19.52 115.56,18.25 IC18.13
N$148
  Top 0.254: LED1.K 119.38,11.27 118.11,12.54 118.11,13.17 IC18.11
N$149
  Bottom 0.254: R12.1 86.99,18.25 88.26,16.98 97.15,16.98 99.69,14.44 118.74,14.44 121.92,11.27 LED1.A
N$150
  Top 0.254: IC21.24 53.34,55.08 53.34,56.35 JP2.1
  Bottom 0.254: R13.2 50.16,57.62 52.7,57.62 JP2.1
N$151  (via drill 0.61)
  Top 0.254: v104.14,6.82 95.25,15.71 95.25,22.06 92.7,24.6 92.7,83.02 88.9,86.83 69.84,86.83 69.84,79.21 68.58,77.94 IC28.1
  Bottom 0.254: v104.14,6.82 114.3,6.82 115.56,5.55 IC18.8
N$153
  Top 0.254: IC20.7 64.13,25.23 65.4,25.23 IC20.8
N$154
  Bottom 0.254: C7.1 56.51,20.79 57.14,21.42 74.29,21.42 74.93,22.06 77.47,22.06 78.1,21.42 78.1,18.88 76.83,18.88 IC27.3
N$155  (via drill 0.61)
  Top 0.254: v59.68,30.95 59.68,28.41 58.41,27.14 IC20.5
  Bottom 0.254: v59.68,30.95 60.32,31.58 67.31,31.58 68.58,32.85 C9.2
N$156
  Bottom 0.254: IC20.4 56.51,26.5 58.41,28.41 67.94,28.41 C9.1
N$157  (via drill 0.61)
  Top 0.254: v53.34,30.95 53.34,27.14 IC20.3
  Bottom 0.254: v53.34,30.95 46.35,30.95 C8.2
N$158
  Top 0.254: C8.1 46.35,25.87 47.62,25.87 IC20.1
N$159
  Top 0.254: C11.1 56.51,23.33 60.32,23.33 60.32,25.23 IC20.6
N$160
  Bottom 0.254: C10.2 48.89,23.33 50.16,24.6 50.79,24.6 IC20.2
NMI\  (via drill 0.61)
  Top 0.254: v27.94,44.92 27.94,65.24 IC17.6
  Bottom 0.254: v27.94,44.92 33.02,39.84 52.06,39.84 52.7,40.48 66.67,40.48 67.94,39.2 IC21.7 69.21,39.2 73.02,43.02 85.09,43.02 85.72,43.65 R6.1
PIA-A0
  Top 0.254: IC25.2 6.98,53.17 2.54,48.73 2.54,44.28 CORE-IO.1
PIA-A1
  Top 0.254: IC25.3 6.98,50.63 5.08,48.73 5.08,44.28 CORE-IO.2
PIA-A2
  Bottom 0.254: IC25.4 6.98,48.09 3.81,44.92 3.81,43.02 2.54,41.74 CORE-IO.3
PIA-A3
  Top 0.254: IC25.5 8.25,45.55 9.52,44.28 9.52,43.02 8.88,42.38 5.08,42.38 5.08,41.74 CORE-IO.4
PIA-A4
  Bottom 0.254: IC25.6 8.25,43.02 9.52,41.74 9.52,39.84 4.44,39.84 3.17,38.57 CORE-IO.5
PIA-A5
  Top 0.254: IC25.7 6.98,40.48 5.71,39.2 5.71,38.57 CORE-IO.6
PIA-A6
  Bottom 0.254: IC25.8 6.98,37.94 6.34,37.3 4.44,37.3 3.17,36.03 CORE-IO.7
PIA-A7
  Top 0.254: IC25.9 6.34,36.03 5.71,36.03 CORE-IO.8
PIA-B0
  Bottom 0.254: IC26.2 6.98,26.5 6.34,27.14 4.44,27.14 3.17,28.41 CORE-IO.13
PIA-B1
  Top 0.254: IC26.3 6.98,22.7 6.34,22.7 5.71,22.06 3.81,22.06 3.81,26.5 5.08,27.77 CORE-IO.14
PIA-B2
  Bottom 0.254: IC26.4 6.98,20.15 6.34,19.52 4.44,19.52 3.81,20.15 3.81,25.23 2.54,25.23 CORE-IO.15
PIA-B3
  Top 0.254: IC26.5 8.25,18.88 9.52,20.15 9.52,23.96 8.88,24.6 5.08,24.6 5.08,25.23 CORE-IO.16
PIA-B4
  Top 0.254: IC26.6 8.25,16.34 10.15,18.25 10.15,28.41 8.88,29.68 1.27,29.68 1.27,25.23 2.54,23.96 CORE-IO.17
PIA-B5
  Bottom 0.254: IC26.7 8.25,13.81 9.52,15.08 9.52,22.06 5.71,22.06 5.08,22.7 CORE-IO.18
PIA-B6
  Bottom 0.254: IC26.8 6.98,11.27 2.54,15.71 2.54,20.15 CORE-IO.19
PIA-B7
  Top 0.254: IC26.9 6.98,8.73 5.08,10.63 5.08,20.15 CORE-IO.20
R/W\  (via drill 0.61)
  Top 0.254: v81.28,41.74 81.28,52.54 IC21.13 80.64,54.45 v74.29,60.8 | 31.75,77.94 31.75,79.21 30.48,80.48 IC17.34 | 31.75,77.94 31.75,65.24 33.02,63.97 33.02,10.63 34.92,8.73 IC24.21 | v38.09,63.97 36.82,65.24 36.82,83.02 36.19,83.66 34.28,83.66 34.28,80.48 31.75,77.94
  Bottom 0.254: v81.28,41.74 86.36,41.74 87.62,43.02 92.07,43.02 93.34,41.74 IC22.27 | v74.29,60.8 41.27,60.8 v38.09,63.97
RST\  (via drill 0.61)
  Top 0.254: v18.41,55.08 17.78,55.71 17.78,63.97 16.51,65.24 16.51,79.21 15.23,80.48 IC17.40 | v40.63,19.52 40.63,41.11 38.09,43.65 37.46,43.65 37.46,43.02 36.19,41.74 IC24.34
  Bottom 0.254: v18.41,55.08 21.59,55.08 34.92,41.74 IC24.34 | v40.63,19.52 65.4,19.52 70.48,14.44 77.47,14.44 82.55,19.52 95.88,19.52 98.42,16.98 123.19,16.98 123.19,10 120.01,6.82 115.56,6.82 114.93,7.46 111.12,7.46 110.48,8.09 IC18.6
RX
  Top 0.254: IC20.12 58.41,34.76 55.88,37.3 IC21.2
RXD
  Top 0.254: IC20.13 55.88,32.22 54.6,30.95 54.6,17.61 53.34,16.34 X1.3
TX
  Top 0.254: IC20.11 60.95,34.76 62.22,36.03 62.22,39.84 62.86,40.48 66.04,40.48 66.04,39.84 IC21.6
TXD
  Top 0.254: IC20.14 53.34,32.22 52.06,30.95 52.06,15.08 52.7,14.44 55.88,14.44 55.88,15.08 X1.2
VCC
  Top 0.508: IC24.24 34.92,15.08 33.65,13.81 33.65,12.54 34.92,11.27 IC24.22 36.82,10.63 44.45,10.63 44.45,25.23 | BYP20.1 43.17,21.42 43.17,22.7 C10.1 43.17,23.96 44.45,25.23 | 46.35,43.65 50.79,39.2 BYP21.1 50.79,37.94 50.79,37.3 48.25,34.76 IC20.16 48.25,32.22 48.25,30.95 44.45,27.14 44.45,25.23 | 46.35,43.65 45.71,44.28 45.71,48.09 R7.2 | 46.35,43.65 46.35,44.28 54.6,52.54 54.6,55.08 55.88,56.35 JP2.2 | R8.2 12.06,76.67 10.79,76.67 R5.2 10.15,76.03 11.42,74.77 11.42,60.8 | IC26.20 15.23,29.04 15.23,30.31 BYP26.1 | IC25.20 15.23,56.98 15.23,58.25 BYP25.1 15.23,59.52 15.23,60.8 11.42,60.8 | 11.42,60.8 8.25,60.8 JP4.2 | 67.31,84.29 67.94,84.29 IC28.16 | 67.31,84.29 66.67,84.29 BYP28.1 | 67.31,84.29 67.31,74.13 68.58,72.86 IC19.16 | BYP29.1 89.53,81.75 90.8,81.75 IC29.28 91.44,80.48 91.44,67.78 IC29.1 91.44,65.24 91.44,62.7 IC23.28 91.44,60.16 91.44,47.46 IC23.1 91.44,44.92 91.44,42.38 IC22.28 | R9.2 84.45,5.55 85.72,4.28 88.9,4.28 88.9,10 R3.2 88.26,10.63 86.99,10.63 R12.2 85.72,10.63 85.72,11.27 84.45,12.54 IC27.10 83.18,13.81 81.91,15.08 81.91,28.41 | R2.2 99.06,18.88 99.06,20.15 R1.2 99.69,20.79 101.59,22.7 BYP17.1 | IC27.14 83.81,23.96 83.81,25.23 BYP27.1 83.81,26.5 81.91,28.41 | R6.2 86.36,50.63 88.9,48.09 88.9,41.74 BYP22.1 | 81.91,28.41 81.28,29.04 81.28,37.3 IC21.12
  Bottom 0.508: R14.2 17.78,6.18 19.05,7.46 19.68,7.46 IC24.20 21.59,8.09 24.12,10.63 34.28,10.63 IC24.22 | IC17.35 27.3,81.11 26.03,81.11 IC17.36 25.39,80.48 21.59,76.67 | 21.59,76.67 13.33,76.67 R8.2 | 21.59,76.67 22.86,76.67 32.38,67.14 IC17.8 33.65,67.14 38.09,71.59 65.4,71.59 BYP19.1 66.67,71.59 67.94,71.59 IC19.16 | 3.17,32.22 2.54,32.85 CORE-IO.9 | 3.17,32.22 4.44,30.95 CORE-IO.12 | 13.33,32.22 14.6,30.95 BYP26.1 | 13.33,32.22 3.17,32.22 | BYP24.1 24.76,58.89 23.49,57.62 17.78,57.62 16.51,56.35 IC25.20 13.96,56.35 13.33,56.35 13.33,32.22 | BYP23.1 86.99,61.43 90.8,61.43 IC23.28 92.07,60.8 93.34,60.8 IC23.27 | IC28.16 69.21,83.66 71.12,81.75 88.26,81.75 BYP29.1 | BYP18.1 106.04,10.63 95.88,10.63 92.07,6.82 89.53,6.82 86.99,4.28 85.72,4.28 84.45,5.55 R9.2 | IC18.14 115.56,20.79 114.3,22.06 103.5,22.06 102.23,23.33 BYP17.1 | IC27.4 76.83,16.34 83.18,22.7 IC27.14 85.09,23.33 95.88,23.33 98.42,20.79 R1.2 | 74.29,40.48 73.02,40.48 71.75,39.2 IC21.8 | 74.29,40.48 75.56,39.2 IC21.10 | 74.29,40.48 79.37,40.48 80.64,39.2 IC21.12 81.91,39.2 83.81,41.11 88.26,41.11 BYP22.1 89.53,41.11 90.8,41.11 IC22.28 | 13.33,32.22 23.49,32.22 31.11,24.6 41.27,24.6 42.54,23.33 C10.1
VMA  (via drill 0.61)
  Top 0.254: v25.39,28.41 25.39,44.92 26.67,46.19 26.67,63.97 25.39,65.24 IC17.5 | v86.99,24.6 92.7,18.88 92.7,15.08 v98.42,9.36
  Bottom 0.254: v25.39,28.41 31.75,22.06 72.39,22.06 74.93,24.6 v86.99,24.6 | v98.42,9.36 114.3,9.36 115.56,8.09 IC18.9

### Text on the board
Top: Component Side
Bottom: Solder side | PA8PDP/VRS
tPlace: RealConsole CORE - Rev.1 | +
tValues: - | +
